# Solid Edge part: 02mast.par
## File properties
Author: User
Template: Iso Metric Part.par
Last saved by: User
Revision: 26
Application: Solid Edge
Accuracy: 0,990
Username: User
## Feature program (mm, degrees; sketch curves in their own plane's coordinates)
lofted protrusion "unnamed LoftedProtrusion 1"
logasc func "Lip_Groove_1"  LipOrGrooveHeight = 1 mm
replace surface "unnamed ReplaceSurface 1"
sketch for "unnamed RevolvedProtrusion 1" plane through (0, 0, 0) normal (0, -1, 0) x-axis (1, 0, 0)
  line (-2.7961, 3.8881) -> (-2.7961, 2.1381)
  line (-2.7961, 2.1381) -> (-3.5461, 2.1381)
  line (-3.5461, 2.1381) -> (-3.5461, 1.6381)
  line (-3.5461, 1.6381) -> (-2.2984, 1.6381)
  line (-2.2984, 1.6381) -> (-2.2961, 3.8881)
  line (-2.2961, 3.8881) -> (-2.7961, 3.8881)
revolve "unnamed RevolvedProtrusion 1" add finite 360 deg
sketch for "ExtrudedProtrusion_1" plane through (0, 0, 2.1381) normal (0, 0, 1) x-axis (1, 0, 0)
  circle centre (-3.1711, 0) radius 0.25
extrude "ExtrudedProtrusion_1" add finite 0.5 along +normal
logasc func "Lip_Groove_2"  LipOrGrooveWidth = 0.35 mm; LipOrGrooveHeight = 0.1 mm
fillet "Round_1" radius 0.15
pattern "unnamed Pattern 1" of "Round_1", "Lip_Groove_2", "ExtrudedProtrusion_1"
pattern "unnamed Pattern 2"
sketch for "ExtrudedProtrusion_2" plane through (0, 0, 0) normal (1, 0, 0) x-axis (0, 1, 0)
  circle centre (0, 49.7231) radius 1.5
extrude "ExtrudedProtrusion_2" add finite 130 along +normal
helix protrusion "HelixProtrusion_5"  NumberOfTurns = 10
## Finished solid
Body 1: sheet body, 1 face, 2 edges, 2 vertices.
  Faces by surface: sphere 1
  Edges by curve: circle 2
Body 2: solid body, 39 faces, 38 edges, 0 vertices.
  Faces by surface: cylinder 15, plane 13, sphere 7, cone 3, spline 1
  Edges by curve: circle 36, intersection 2
Bounding box of the edges (mm; curved faces can reach further): 133.546 x 7.092 x 300.002, from (-3.5461, -3.5461, 0) to (130, 3.5461, 300.0015).
Cylindrical faces by radius (mm): R0.15 x6, R0.25 x6, R1.5 x1, R2.7961 x1, R3.5461 x1
Conical faces (half-angle, radius in mm at the cone's reference point): 0.0573 deg R1.8 x1, 0.0573 deg R2.3 x2
Spherical faces by radius (mm): R0.15 x6, R1.5 x2
Planar faces by outward normal: +x 1, +y 1, +z 9, -z 2
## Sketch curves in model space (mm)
line (130.4204, 0, 49.7231) -> (2.2518, 0, 49.7231)
circle centre (129.8613, 0, 48.111) radius 0.0992
line (130, 0, 49.7231) -> (0.86, 0, 49.7231)
circle centre (129.6413, -1.8169, 49.7231) radius 0.3169
line (0, 0, 4.0503) -> (0, 0, 1.6561)
line (-2.7961, 0, 3.8881) -> (-2.7961, 0, 2.1381)
line (-2.7961, 0, 2.1381) -> (-3.5461, 0, 2.1381)
line (-3.5461, 0, 2.1381) -> (-3.5461, 0, 1.6381)
line (-3.5461, 0, 1.6381) -> (-2.2984, 0, 1.6381)
line (-2.2984, 0, 1.6381) -> (-2.2961, 0, 3.8881)
line (-2.2961, 0, 3.8881) -> (-2.7961, 0, 3.8881)
circle centre (0, 0, 300) radius 1.5
arc centre (0, 0, 300) radius 1.5 from (-1.5, 0, 300) through (0.0444, 0, 301.4993) to (1.5, 0, 300)
circle centre (0, 0, 300) radius 2
circle centre (0, 0, 0) radius 2.3
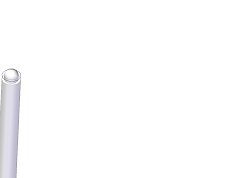
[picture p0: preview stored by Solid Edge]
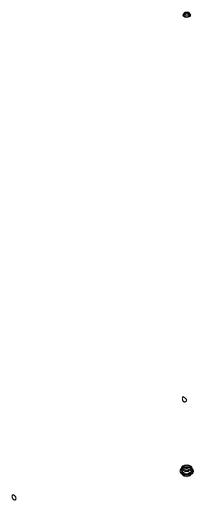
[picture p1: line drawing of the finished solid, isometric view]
